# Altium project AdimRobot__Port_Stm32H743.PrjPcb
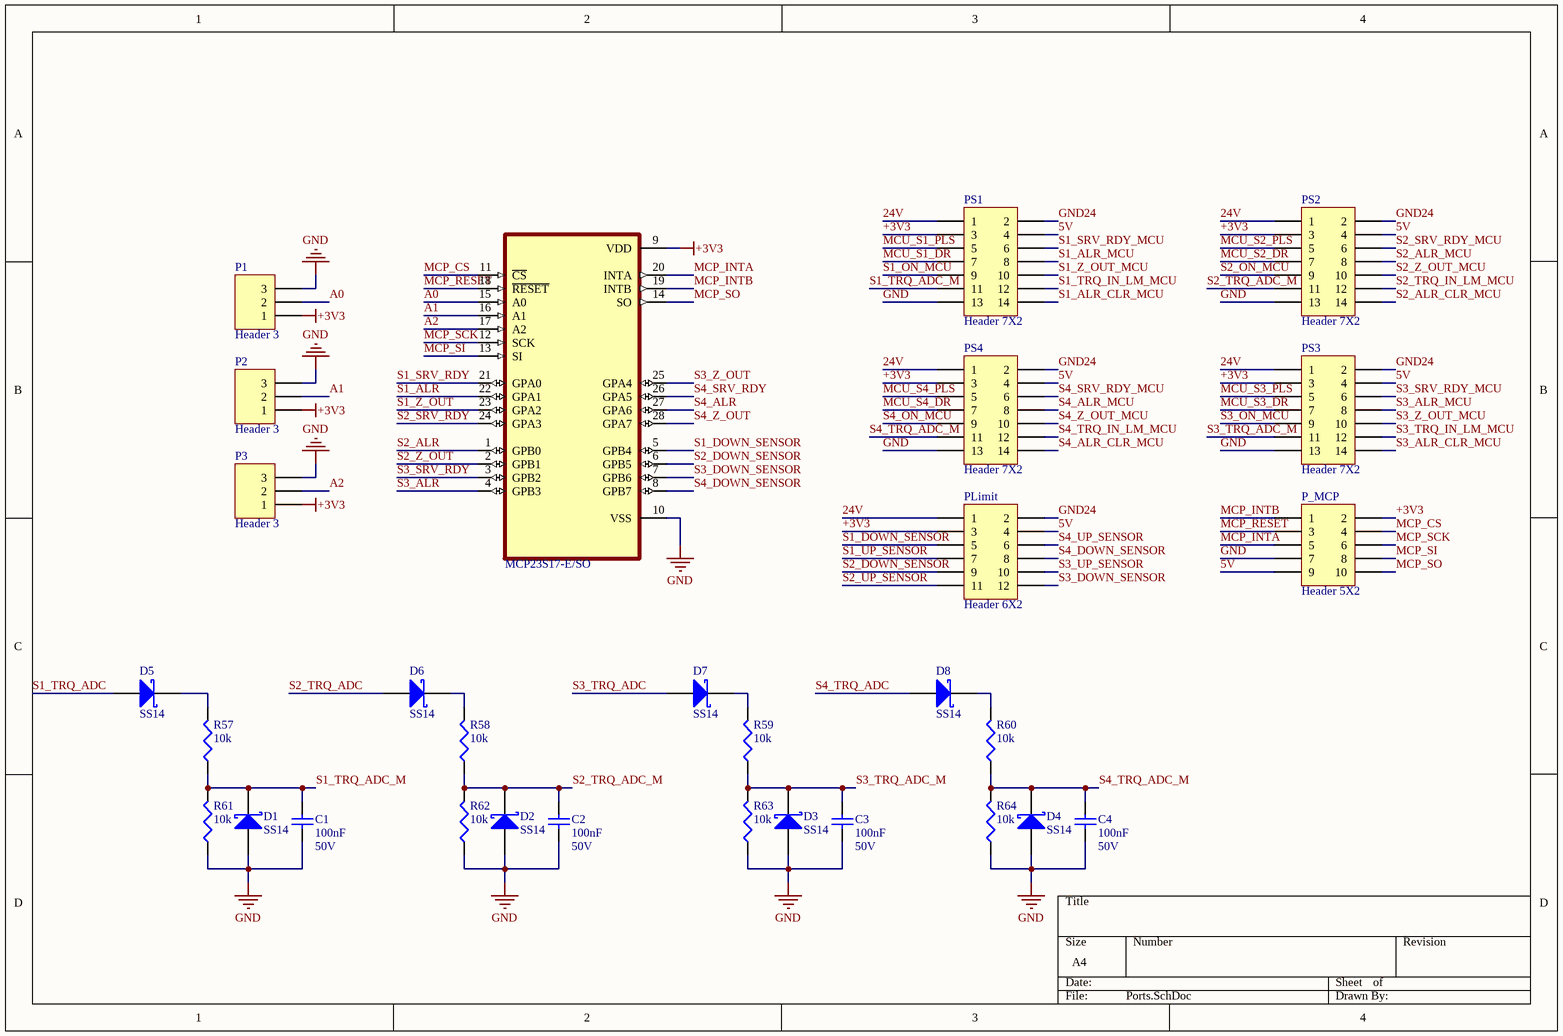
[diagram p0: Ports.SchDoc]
3 sheets, 116 parts. Net scope: global (net labels, ports and power ports of the same name join across sheets).
Board file: Ports.PcbDoc
Sheets:
  Ports.SchDoc
  D-Sub15.SchDoc
  Optic.SchDoc

## Sheet Ports.SchDoc
size A4

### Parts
C1  100nF  Potential: 50V  [CAP0805]
C2  100nF  Potential: 50V  [CAP0805]
C3  100nF  Potential: 50V  [CAP0805]
C4  100nF  Potential: 50V  [CAP0805]
D1  SS14  [DO-214AA]
D2  SS14  [DO-214AA]
D3  SS14  [DO-214AA]
D4  SS14  [DO-214AA]
D5  SS14  [DO-214AA]
D6  SS14  [DO-214AA]
D7  SS14  [DO-214AA]
D8  SS14  [DO-214AA]
P1  Header 3  [HDR1X3]
P2  Header 3  [HDR1X3]
P3  Header 3  [HDR1X3]
P_MCP  Header 5X2  [HDR2X5]
PLimit  Header 6X2  [HDR2X6]
PS1  Header 7X2  [HDR2X7]
PS2  Header 7X2  [HDR2X7]
PS3  Header 7X2  [HDR2X7]
PS4  Header 7X2  [HDR2X7]
R57  10k  [Res0805]
R58  10k  [Res0805]
R59  10k  [Res0805]
R60  10k  [Res0805]
R61  10k  [Res0805]
R62  10k  [Res0805]
R63  10k  [Res0805]
R64  10k  [Res0805]
  MCP23S17-E/SO  [SOIC127P1030X265-28N]

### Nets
24V: PLimit.1 PS1.1 PS2.1 PS3.1 PS4.1
+3V3: P1.1 P2.1 P3.1 P_MCP.2 PLimit.3 PS1.3 PS2.3 PS3.3 PS4.3 .9(VDD)
GND: C1.1 C2.1 C3.1 C4.1 D1.1(A) D2.1(A) D3.1(A) D4.1(A) P1.3 P2.3 P3.3 P_MCP.7 PS1.13 PS2.13 PS3.13 PS4.13 R61.1 R62.1 R63.1 R64.1 .10(VSS)
GND24: PLimit.2 PS1.2 PS2.2 PS3.2 PS4.2
5V: P_MCP.9 PLimit.4 PS1.4 PS2.4 PS3.4 PS4.4
A0: P1.2 .15(A0)
A1: P2.2 .16(A1)
A2: P3.2 .17(A2)
MCP_CS: P_MCP.4 .11(~{CS})
MCP_INTA: P_MCP.5 .20(INTA)
MCP_INTB: P_MCP.1 .19(INTB)
MCP_RESET: P_MCP.3 .18(~{RESET})
MCP_SCK: P_MCP.6 .12(SCK)
MCP_SI: P_MCP.8 .13(SI)
MCP_SO: P_MCP.10 .14(SO)
MCU_S1_DR: PS1.7
MCU_S1_PLS: PS1.5
MCU_S2_DR: PS2.7
MCU_S2_PLS: PS2.5
MCU_S3_DR: PS3.7
MCU_S3_PLS: PS3.5
MCU_S4_DR: PS4.7
MCU_S4_PLS: PS4.5
S1_ALR: .22(GPA1)
S1_ALR_CLR_MCU: PS1.14
S1_ALR_MCU: PS1.8
S1_DOWN_SENSOR: PLimit.5 .5(GPB4)
S1_ON_MCU: PS1.9
S1_SRV_RDY: .21(GPA0)
S1_SRV_RDY_MCU: PS1.6
S1_TRQ_ADC: D5.1(A)
S1_TRQ_ADC_M: C1.2 D1.2(K) PS1.11 R57.1 R61.2
S1_TRQ_IN_LM_MCU: PS1.12
S1_UP_SENSOR: PLimit.7
S1_Z_OUT: .23(GPA2)
S1_Z_OUT_MCU: PS1.10
S2_ALR: .1(GPB0)
S2_ALR_CLR_MCU: PS2.14
S2_ALR_MCU: PS2.8
S2_DOWN_SENSOR: PLimit.9 .6(GPB5)
S2_ON_MCU: PS2.9
S2_SRV_RDY: .24(GPA3)
S2_SRV_RDY_MCU: PS2.6
S2_TRQ_ADC: D6.1(A)
S2_TRQ_ADC_M: C2.2 D2.2(K) PS2.11 R58.1 R62.2
S2_TRQ_IN_LM_MCU: PS2.12
S2_UP_SENSOR: PLimit.11
S2_Z_OUT: .2(GPB1)
S2_Z_OUT_MCU: PS2.10
S3_ALR: .4(GPB3)
S3_ALR_CLR_MCU: PS3.14
S3_ALR_MCU: PS3.8
S3_DOWN_SENSOR: PLimit.12 .7(GPB6)
S3_ON_MCU: PS3.9
S3_SRV_RDY: .3(GPB2)
S3_SRV_RDY_MCU: PS3.6
S3_TRQ_ADC: D7.1(A)
S3_TRQ_ADC_M: C3.2 D3.2(K) PS3.11 R59.1 R63.2
S3_TRQ_IN_LM_MCU: PS3.12
S3_UP_SENSOR: PLimit.10
S3_Z_OUT: .25(GPA4)
S3_Z_OUT_MCU: PS3.10
S4_ALR: .27(GPA6)
S4_ALR_CLR_MCU: PS4.14
S4_ALR_MCU: PS4.8
S4_DOWN_SENSOR: PLimit.8 .8(GPB7)
S4_ON_MCU: PS4.9
S4_SRV_RDY: .26(GPA5)
S4_SRV_RDY_MCU: PS4.6
S4_TRQ_ADC: D8.1(A)
S4_TRQ_ADC_M: C4.2 D4.2(K) PS4.11 R60.1 R64.2
S4_TRQ_IN_LM_MCU: PS4.12
S4_UP_SENSOR: PLimit.6
S4_Z_OUT: .28(GPA7)
S4_Z_OUT_MCU: PS4.10
NetD5_2: D5.2(K) R57.2
NetD6_2: D6.2(K) R58.2
NetD7_2: D7.2(K) R59.2
NetD8_2: D8.2(K) R60.2

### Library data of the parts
C1-C4 = 100nF: 100nF 50V,  X7R, ±10%, Ceramic Capacitor; Manufacturer: SAMSUNG; Manufacturer Part Number: CL21B104KBCNNNC; Capacitance (Farads): 100n
D1-D8 = SS14: 1A 40V Schottky Diode; Manufacturer: PANJIT; Vfw: 0.5V
P1-P3 = Header 3: Header, 3-Pin
P_MCP = Header 5X2: Header, 5-Pin, Dual row
PLimit = Header 6X2: Header, 6-Pin, Dual row
PS1-PS4 = Header 7X2: Header, 7-Pin, Dual row
R57-R64 = 10k OHM: RES 10k OHM 1/8W 5% 0805 SMD; Manufacturer: Royalohm; Manufacturer Part Number: 0805S8F1002TDE; Power (Watts): 1/8W , 0.125W
 = MCP23S17-E/SO: I/O Expander 16 SPI 10MHz 28-SOIC; MF: Microchip

## Sheet D-Sub15.SchDoc
size A4
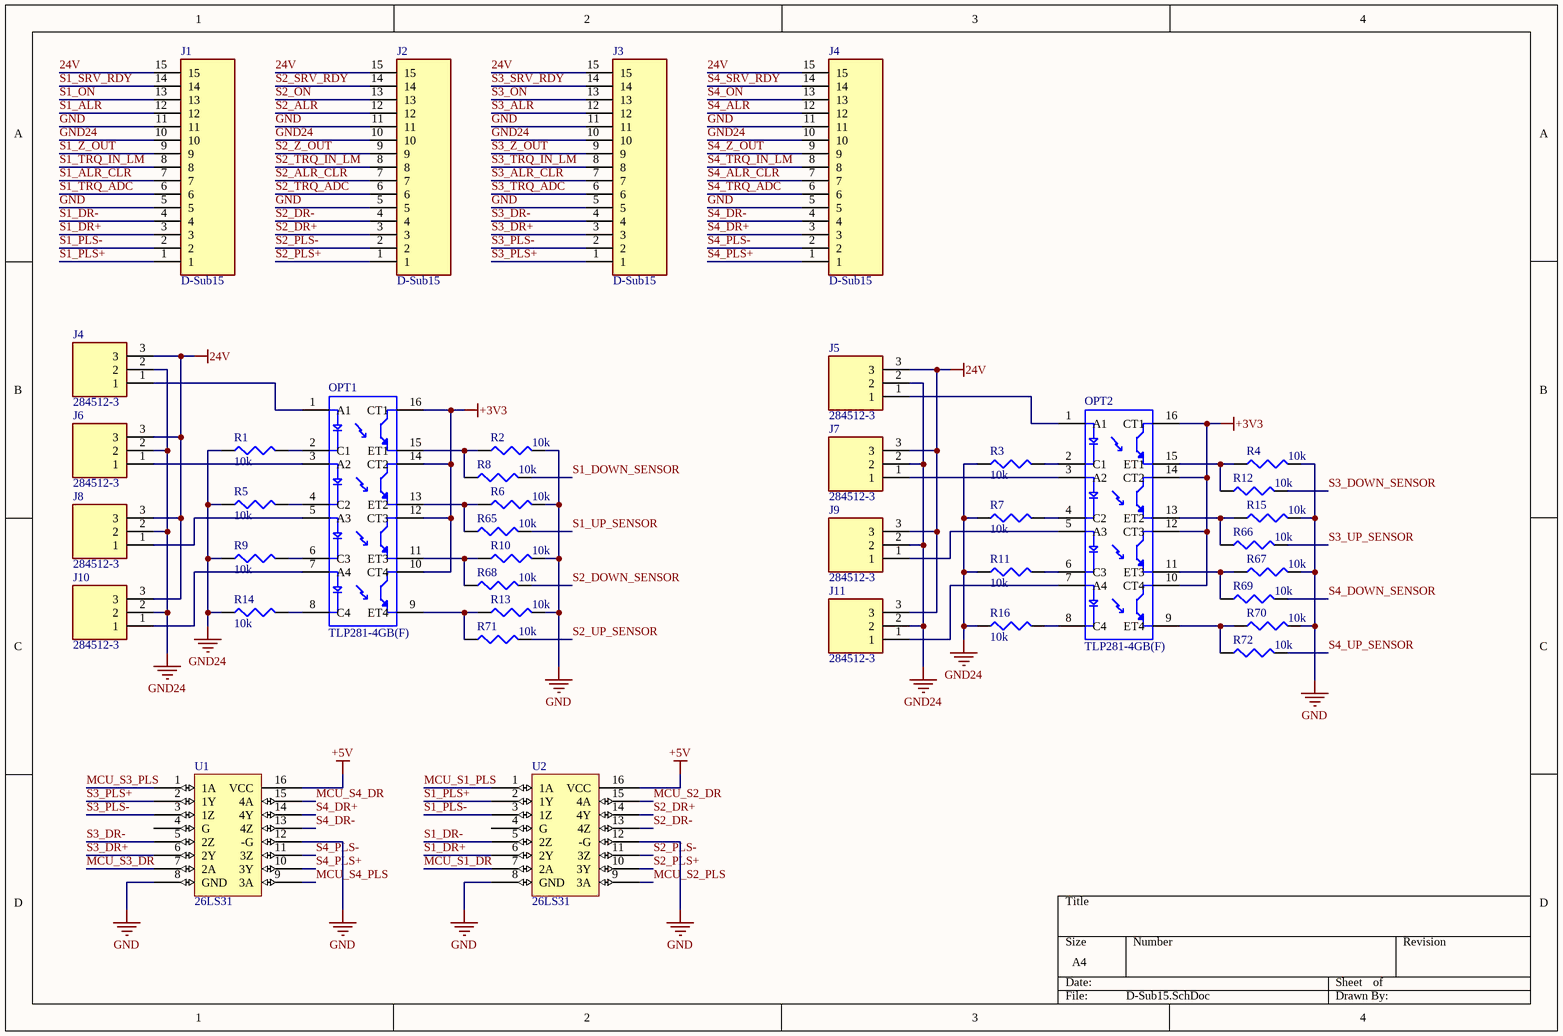
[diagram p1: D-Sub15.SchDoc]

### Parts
(Parts that share a designator on the sheet are numbered #1, #2 ... from top to bottom, then left to right.)
J1  D-Sub15  [D-Sub15]
J2  D-Sub15  [D-Sub15]
J3  D-Sub15  [D-Sub15]
J4#1  D-Sub15  [D-Sub15]
J4#2  284512-3  [TE_284512-3]
J5  284512-3  [TE_284512-3]
J6  284512-3  [TE_284512-3]
J7  284512-3  [TE_284512-3]
J8  284512-3  [TE_284512-3]
J9  284512-3  [TE_284512-3]
J10  284512-3  [TE_284512-3]
J11  284512-3  [TE_284512-3]
OPT1  TLP281-4GB(F)  [SOIC127P700X210-16N]
OPT2  TLP281-4GB(F)  [SOIC127P700X210-16N]
R1  10k  [Res0805]
R2  10k  [Res0805]
R3  10k  [Res0805]
R4  10k  [Res0805]
R5  10k  [Res0805]
R6  10k  [Res0805]
R7  10k  [Res0805]
R8  10k  [Res0805]
R9  10k  [Res0805]
R10  10k  [Res0805]
R11  10k  [Res0805]
R12  10k  [Res0805]
R13  10k  [Res0805]
R14  10k  [Res0805]
R15  10k  [Res0805]
R16  10k  [Res0805]
R65  10k  [Res0805]
R66  10k  [Res0805]
R67  10k  [Res0805]
R68  10k  [Res0805]
R69  10k  [Res0805]
R70  10k  [Res0805]
R71  10k  [Res0805]
R72  10k  [Res0805]
U1  26LS31  [26LS31]
U2  26LS31  [26LS31]

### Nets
24V: J1.15 J2.15 J3.15 J4#1.15 J4#2.3 J5.3 J6.3 J7.3 J8.3 J9.3 J10.3 J11.3
+3V3: OPT1.10(CT4) OPT1.12(CT3) OPT1.14(CT2) OPT1.16(CT1) OPT2.10(CT4) OPT2.12(CT3) OPT2.14(CT2) OPT2.16(CT1)
+5V: U1.16(VCC) U2.16(VCC)
GND: J1.5 J1.11 J2.5 J2.11 J3.5 J3.11 J4#1.5 J4#1.11 R2.2 R4.2 R6.2 R10.2 R13.2 R15.2 R67.2 R70.2 U1.8(GND) U1.12(-G) U2.8(GND) U2.12(-G)
GND24: J1.10 J2.10 J3.10 J4#1.10 J4#2.2 J5.2 J6.2 J7.2 J8.2 J9.2 J10.2 J11.2 R1.1 R3.1 R5.1 R7.1 R9.1 R11.1 R14.1 R16.1
MCU_S1_DR: U2.7(2A)
MCU_S1_PLS: U2.1(1A)
MCU_S2_DR: U2.15(4A)
MCU_S2_PLS: U2.9(3A)
MCU_S3_DR: U1.7(2A)
MCU_S3_PLS: U1.1(1A)
MCU_S4_DR: U1.15(4A)
MCU_S4_PLS: U1.9(3A)
S1_ALR: J1.12
S1_ALR_CLR: J1.7
S1_DOWN_SENSOR: R8.2
S1_DR+: J1.3 U2.6(2Y)
S1_DR-: J1.4 U2.5(2Z)
S1_ON: J1.13
S1_PLS+: J1.1 U2.2(1Y)
S1_PLS-: J1.2 U2.3(1Z)
S1_SRV_RDY: J1.14
S1_TRQ_ADC: J1.6
S1_TRQ_IN_LM: J1.8
S1_UP_SENSOR: R65.2
S1_Z_OUT: J1.9
S2_ALR: J2.12
S2_ALR_CLR: J2.7
S2_DOWN_SENSOR: R68.2
S2_DR+: J2.3 U2.14(4Y)
S2_DR-: J2.4 U2.13(4Z)
S2_ON: J2.13
S2_PLS+: J2.1 U2.10(3Y)
S2_PLS-: J2.2 U2.11(3Z)
S2_SRV_RDY: J2.14
S2_TRQ_ADC: J2.6
S2_TRQ_IN_LM: J2.8
S2_UP_SENSOR: R71.2
S2_Z_OUT: J2.9
S3_ALR: J3.12
S3_ALR_CLR: J3.7
S3_DOWN_SENSOR: R12.2
S3_DR+: J3.3 U1.6(2Y)
S3_DR-: J3.4 U1.5(2Z)
S3_ON: J3.13
S3_PLS+: J3.1 U1.2(1Y)
S3_PLS-: J3.2 U1.3(1Z)
S3_SRV_RDY: J3.14
S3_TRQ_ADC: J3.6
S3_TRQ_IN_LM: J3.8
S3_UP_SENSOR: R66.2
S3_Z_OUT: J3.9
S4_ALR: J4#1.12
S4_ALR_CLR: J4#1.7
S4_DOWN_SENSOR: R69.2
S4_DR+: J4#1.3 U1.14(4Y)
S4_DR-: J4#1.4 U1.13(4Z)
S4_ON: J4#1.13
S4_PLS+: J4#1.1 U1.10(3Y)
S4_PLS-: J4#1.2 U1.11(3Z)
S4_SRV_RDY: J4#1.14
S4_TRQ_ADC: J4#1.6
S4_TRQ_IN_LM: J4#1.8
S4_UP_SENSOR: R72.2
S4_Z_OUT: J4#1.9
NetJ4#2_1: J4#2.1 OPT1.1(A1)
NetJ5_1: J5.1 OPT2.1(A1)
NetJ6_1: J6.1 OPT1.3(A2)
NetJ7_1: J7.1 OPT2.3(A2)
NetJ8_1: J8.1 OPT1.5(A3)
NetJ9_1: J9.1 OPT2.5(A3)
NetJ10_1: J10.1 OPT1.7(A4)
NetJ11_1: J11.1 OPT2.7(A4)
NetOPT1_2: OPT1.2(C1) R1.2
NetOPT1_4: OPT1.4(C2) R5.2
NetOPT1_6: OPT1.6(C3) R9.2
NetOPT1_8: OPT1.8(C4) R14.2
NetOPT1_9: OPT1.9(ET4) R13.1 R71.1
NetOPT1_11: OPT1.11(ET3) R10.1 R68.1
NetOPT1_13: OPT1.13(ET2) R6.1 R65.1
NetOPT1_15: OPT1.15(ET1) R2.1 R8.1
NetOPT2_2: OPT2.2(C1) R3.2
NetOPT2_4: OPT2.4(C2) R7.2
NetOPT2_6: OPT2.6(C3) R11.2
NetOPT2_8: OPT2.8(C4) R16.2
NetOPT2_9: OPT2.9(ET4) R70.1 R72.1
NetOPT2_11: OPT2.11(ET3) R67.1 R69.1
NetOPT2_13: OPT2.13(ET2) R15.1 R66.1
NetOPT2_15: OPT2.15(ET1) R4.1 R12.1

Not connected (* = marked no-connect by the designer): U1 4(G); U2 4(G)

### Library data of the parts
J1-J3 J4#1 = D-Sub15: 15 Position D-Sub, High Density Receptacle, Female Sockets Connector; MF: NorComp Inc.; MP: 181-015-213R561
J4#2 J5-J11 = 284512-3: Pluggable terminal block; socket; male; angled; 3.5mm;; MF: TE Connectivity; Centerline_Pitch: 3.5 mm[.138 in]; Number_of_Positions: 3
OPT1 OPT2 = TLP281-4GB(F): Optocoupler DC-IN 4-CH Transistor DC-OUT 16-Pin SOP; MP: TLP281-4GB_F_; MF: Toshiba
R1-R16 R65-R72 = 10k OHM: as R57 on sheet Ports
U1 U2 = 26LS31: BUS DRIVER; PackageDocument: 1994

## Sheet Optic.SchDoc
size A4
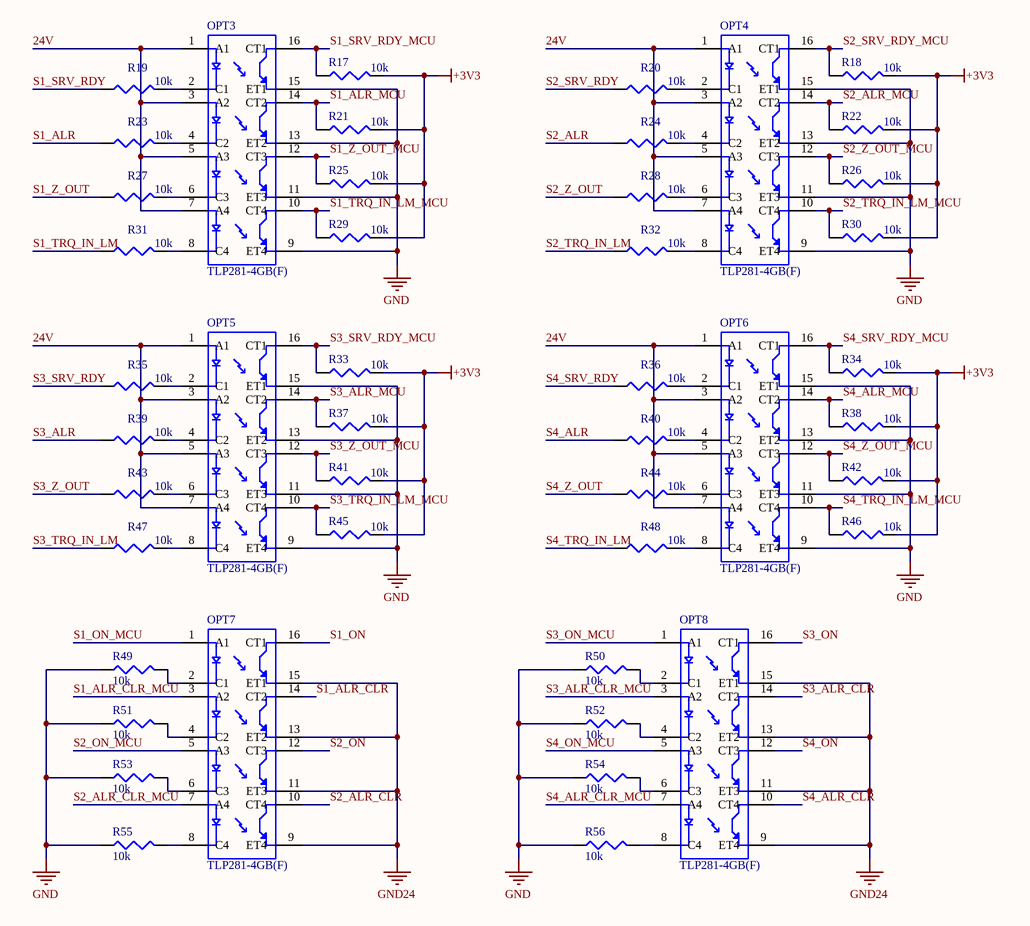
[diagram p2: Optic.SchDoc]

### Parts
OPT3  TLP281-4GB(F)  [SOIC127P700X210-16N]
OPT4  TLP281-4GB(F)  [SOIC127P700X210-16N]
OPT5  TLP281-4GB(F)  [SOIC127P700X210-16N]
OPT6  TLP281-4GB(F)  [SOIC127P700X210-16N]
OPT7  TLP281-4GB(F)  [SOIC127P700X210-16N]
OPT8  TLP281-4GB(F)  [SOIC127P700X210-16N]
R17  10k  [Res0805]
R18  10k  [Res0805]
R19  10k  [Res0805]
R20  10k  [Res0805]
R21  10k  [Res0805]
R22  10k  [Res0805]
R23  10k  [Res0805]
R24  10k  [Res0805]
R25  10k  [Res0805]
R26  10k  [Res0805]
R27  10k  [Res0805]
R28  10k  [Res0805]
R29  10k  [Res0805]
R30  10k  [Res0805]
R31  10k  [Res0805]
R32  10k  [Res0805]
R33  10k  [Res0805]
R34  10k  [Res0805]
R35  10k  [Res0805]
R36  10k  [Res0805]
R37  10k  [Res0805]
R38  10k  [Res0805]
R39  10k  [Res0805]
R40  10k  [Res0805]
R41  10k  [Res0805]
R42  10k  [Res0805]
R43  10k  [Res0805]
R44  10k  [Res0805]
R45  10k  [Res0805]
R46  10k  [Res0805]
R47  10k  [Res0805]
R48  10k  [Res0805]
R49  10k  [Res0805]
R50  10k  [Res0805]
R51  10k  [Res0805]
R52  10k  [Res0805]
R53  10k  [Res0805]
R54  10k  [Res0805]
R55  10k  [Res0805]
R56  10k  [Res0805]

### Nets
24V: OPT3.1(A1) OPT3.3(A2) OPT3.5(A3) OPT3.7(A4) OPT4.1(A1) OPT4.3(A2) OPT4.5(A3) OPT4.7(A4) OPT5.1(A1) OPT5.3(A2) OPT5.5(A3) OPT5.7(A4) OPT6.1(A1) OPT6.3(A2) OPT6.5(A3) OPT6.7(A4)
+3V3: R17.2 R18.2 R21.2 R22.2 R25.2 R26.2 R29.2 R30.2 R33.2 R34.2 R37.2 R38.2 R41.2 R42.2 R45.2 R46.2
GND: OPT3.9(ET4) OPT3.11(ET3) OPT3.13(ET2) OPT3.15(ET1) OPT4.9(ET4) OPT4.11(ET3) OPT4.13(ET2) OPT4.15(ET1) OPT5.9(ET4) OPT5.11(ET3) OPT5.13(ET2) OPT5.15(ET1) OPT6.9(ET4) OPT6.11(ET3) OPT6.13(ET2) OPT6.15(ET1) R49.1 R50.1 R51.1 R52.1 R53.1 R54.1 R55.1 R56.1
GND24: OPT7.9(ET4) OPT7.11(ET3) OPT7.13(ET2) OPT7.15(ET1) OPT8.9(ET4) OPT8.11(ET3) OPT8.13(ET2) OPT8.15(ET1)
S1_ALR: R23.1
S1_ALR_CLR: OPT7.14(CT2)
S1_ALR_CLR_MCU: OPT7.3(A2)
S1_ALR_MCU: OPT3.14(CT2) R21.1
S1_ON: OPT7.16(CT1)
S1_ON_MCU: OPT7.1(A1)
S1_SRV_RDY: R19.1
S1_SRV_RDY_MCU: OPT3.16(CT1) R17.1
S1_TRQ_IN_LM: R31.1
S1_TRQ_IN_LM_MCU: OPT3.10(CT4) R29.1
S1_Z_OUT: R27.1
S1_Z_OUT_MCU: OPT3.12(CT3) R25.1
S2_ALR: R24.1
S2_ALR_CLR: OPT7.10(CT4)
S2_ALR_CLR_MCU: OPT7.7(A4)
S2_ALR_MCU: OPT4.14(CT2) R22.1
S2_ON: OPT7.12(CT3)
S2_ON_MCU: OPT7.5(A3)
S2_SRV_RDY: R20.1
S2_SRV_RDY_MCU: OPT4.16(CT1) R18.1
S2_TRQ_IN_LM: R32.1
S2_TRQ_IN_LM_MCU: OPT4.10(CT4) R30.1
S2_Z_OUT: R28.1
S2_Z_OUT_MCU: OPT4.12(CT3) R26.1
S3_ALR: R39.1
S3_ALR_CLR: OPT8.14(CT2)
S3_ALR_CLR_MCU: OPT8.3(A2)
S3_ALR_MCU: OPT5.14(CT2) R37.1
S3_ON: OPT8.16(CT1)
S3_ON_MCU: OPT8.1(A1)
S3_SRV_RDY: R35.1
S3_SRV_RDY_MCU: OPT5.16(CT1) R33.1
S3_TRQ_IN_LM: R47.1
S3_TRQ_IN_LM_MCU: OPT5.10(CT4) R45.1
S3_Z_OUT: R43.1
S3_Z_OUT_MCU: OPT5.12(CT3) R41.1
S4_ALR: R40.1
S4_ALR_CLR: OPT8.10(CT4)
S4_ALR_CLR_MCU: OPT8.7(A4)
S4_ALR_MCU: OPT6.14(CT2) R38.1
S4_ON: OPT8.12(CT3)
S4_ON_MCU: OPT8.5(A3)
S4_SRV_RDY: R36.1
S4_SRV_RDY_MCU: OPT6.16(CT1) R34.1
S4_TRQ_IN_LM: R48.1
S4_TRQ_IN_LM_MCU: OPT6.10(CT4) R46.1
S4_Z_OUT: R44.1
S4_Z_OUT_MCU: OPT6.12(CT3) R42.1
NetOPT3_2: OPT3.2(C1) R19.2
NetOPT3_4: OPT3.4(C2) R23.2
NetOPT3_6: OPT3.6(C3) R27.2
NetOPT3_8: OPT3.8(C4) R31.2
NetOPT4_2: OPT4.2(C1) R20.2
NetOPT4_4: OPT4.4(C2) R24.2
NetOPT4_6: OPT4.6(C3) R28.2
NetOPT4_8: OPT4.8(C4) R32.2
NetOPT5_2: OPT5.2(C1) R35.2
NetOPT5_4: OPT5.4(C2) R39.2
NetOPT5_6: OPT5.6(C3) R43.2
NetOPT5_8: OPT5.8(C4) R47.2
NetOPT6_2: OPT6.2(C1) R36.2
NetOPT6_4: OPT6.4(C2) R40.2
NetOPT6_6: OPT6.6(C3) R44.2
NetOPT6_8: OPT6.8(C4) R48.2
NetOPT7_2: OPT7.2(C1) R49.2
NetOPT7_4: OPT7.4(C2) R51.2
NetOPT7_6: OPT7.6(C3) R53.2
NetOPT7_8: OPT7.8(C4) R55.2
NetOPT8_2: OPT8.2(C1) R50.2
NetOPT8_4: OPT8.4(C2) R52.2
NetOPT8_6: OPT8.6(C3) R54.2
NetOPT8_8: OPT8.8(C4) R56.2

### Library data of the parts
OPT3-OPT8 = TLP281-4GB(F): as OPT1 on sheet D-Sub15
R17-R56 = 10k OHM: as R57 on sheet Ports

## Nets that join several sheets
24V: Ports (5 pins), D-Sub15 (12 pins), Optic (16 pins)
+3V3: Ports (10 pins), D-Sub15 (8 pins), Optic (16 pins)
GND: Ports (21 pins), D-Sub15 (20 pins), Optic (24 pins)
GND24: Ports (5 pins), D-Sub15 (20 pins), Optic (8 pins)
MCU_S1_DR: Ports (PS1.7), D-Sub15 (U2.7)
MCU_S1_PLS: Ports (PS1.5), D-Sub15 (U2.1)
MCU_S2_DR: Ports (PS2.7), D-Sub15 (U2.15)
MCU_S2_PLS: Ports (PS2.5), D-Sub15 (U2.9)
MCU_S3_DR: Ports (PS3.7), D-Sub15 (U1.7)
MCU_S3_PLS: Ports (PS3.5), D-Sub15 (U1.1)
MCU_S4_DR: Ports (PS4.7), D-Sub15 (U1.15)
MCU_S4_PLS: Ports (PS4.5), D-Sub15 (U1.9)
S1_ALR: Ports (.22), D-Sub15 (J1.12), Optic (R23.1)
S1_ALR_CLR: D-Sub15 (J1.7), Optic (OPT7.14)
S1_ALR_CLR_MCU: Ports (PS1.14), Optic (OPT7.3)
S1_ALR_MCU: Ports (PS1.8), Optic (OPT3.14 R21.1)
S1_DOWN_SENSOR: Ports (PLimit.5 .5), D-Sub15 (R8.2)
S1_ON: D-Sub15 (J1.13), Optic (OPT7.16)
S1_ON_MCU: Ports (PS1.9), Optic (OPT7.1)
S1_SRV_RDY: Ports (.21), D-Sub15 (J1.14), Optic (R19.1)
S1_SRV_RDY_MCU: Ports (PS1.6), Optic (OPT3.16 R17.1)
S1_TRQ_ADC: Ports (D5.1), D-Sub15 (J1.6)
S1_TRQ_IN_LM: D-Sub15 (J1.8), Optic (R31.1)
S1_TRQ_IN_LM_MCU: Ports (PS1.12), Optic (OPT3.10 R29.1)
S1_UP_SENSOR: Ports (PLimit.7), D-Sub15 (R65.2)
S1_Z_OUT: Ports (.23), D-Sub15 (J1.9), Optic (R27.1)
S1_Z_OUT_MCU: Ports (PS1.10), Optic (OPT3.12 R25.1)
S2_ALR: Ports (.1), D-Sub15 (J2.12), Optic (R24.1)
S2_ALR_CLR: D-Sub15 (J2.7), Optic (OPT7.10)
S2_ALR_CLR_MCU: Ports (PS2.14), Optic (OPT7.7)
S2_ALR_MCU: Ports (PS2.8), Optic (OPT4.14 R22.1)
S2_DOWN_SENSOR: Ports (PLimit.9 .6), D-Sub15 (R68.2)
S2_ON: D-Sub15 (J2.13), Optic (OPT7.12)
S2_ON_MCU: Ports (PS2.9), Optic (OPT7.5)
S2_SRV_RDY: Ports (.24), D-Sub15 (J2.14), Optic (R20.1)
S2_SRV_RDY_MCU: Ports (PS2.6), Optic (OPT4.16 R18.1)
S2_TRQ_ADC: Ports (D6.1), D-Sub15 (J2.6)
S2_TRQ_IN_LM: D-Sub15 (J2.8), Optic (R32.1)
S2_TRQ_IN_LM_MCU: Ports (PS2.12), Optic (OPT4.10 R30.1)
S2_UP_SENSOR: Ports (PLimit.11), D-Sub15 (R71.2)
S2_Z_OUT: Ports (.2), D-Sub15 (J2.9), Optic (R28.1)
S2_Z_OUT_MCU: Ports (PS2.10), Optic (OPT4.12 R26.1)
S3_ALR: Ports (.4), D-Sub15 (J3.12), Optic (R39.1)
S3_ALR_CLR: D-Sub15 (J3.7), Optic (OPT8.14)
S3_ALR_CLR_MCU: Ports (PS3.14), Optic (OPT8.3)
S3_ALR_MCU: Ports (PS3.8), Optic (OPT5.14 R37.1)
S3_DOWN_SENSOR: Ports (PLimit.12 .7), D-Sub15 (R12.2)
S3_ON: D-Sub15 (J3.13), Optic (OPT8.16)
S3_ON_MCU: Ports (PS3.9), Optic (OPT8.1)
S3_SRV_RDY: Ports (.3), D-Sub15 (J3.14), Optic (R35.1)
S3_SRV_RDY_MCU: Ports (PS3.6), Optic (OPT5.16 R33.1)
S3_TRQ_ADC: Ports (D7.1), D-Sub15 (J3.6)
S3_TRQ_IN_LM: D-Sub15 (J3.8), Optic (R47.1)
S3_TRQ_IN_LM_MCU: Ports (PS3.12), Optic (OPT5.10 R45.1)
S3_UP_SENSOR: Ports (PLimit.10), D-Sub15 (R66.2)
S3_Z_OUT: Ports (.25), D-Sub15 (J3.9), Optic (R43.1)
S3_Z_OUT_MCU: Ports (PS3.10), Optic (OPT5.12 R41.1)
S4_ALR: Ports (.27), D-Sub15 (J4#1.12), Optic (R40.1)
S4_ALR_CLR: D-Sub15 (J4#1.7), Optic (OPT8.10)
S4_ALR_CLR_MCU: Ports (PS4.14), Optic (OPT8.7)
S4_ALR_MCU: Ports (PS4.8), Optic (OPT6.14 R38.1)
S4_DOWN_SENSOR: Ports (PLimit.8 .8), D-Sub15 (R69.2)
S4_ON: D-Sub15 (J4#1.13), Optic (OPT8.12)
S4_ON_MCU: Ports (PS4.9), Optic (OPT8.5)
S4_SRV_RDY: Ports (.26), D-Sub15 (J4#1.14), Optic (R36.1)
S4_SRV_RDY_MCU: Ports (PS4.6), Optic (OPT6.16 R34.1)
S4_TRQ_ADC: Ports (D8.1), D-Sub15 (J4#1.6)
S4_TRQ_IN_LM: D-Sub15 (J4#1.8), Optic (R48.1)
S4_TRQ_IN_LM_MCU: Ports (PS4.12), Optic (OPT6.10 R46.1)
S4_UP_SENSOR: Ports (PLimit.6), D-Sub15 (R72.2)
S4_Z_OUT: Ports (.28), D-Sub15 (J4#1.9), Optic (R44.1)
S4_Z_OUT_MCU: Ports (PS4.10), Optic (OPT6.12 R42.1)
